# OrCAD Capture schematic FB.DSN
size C
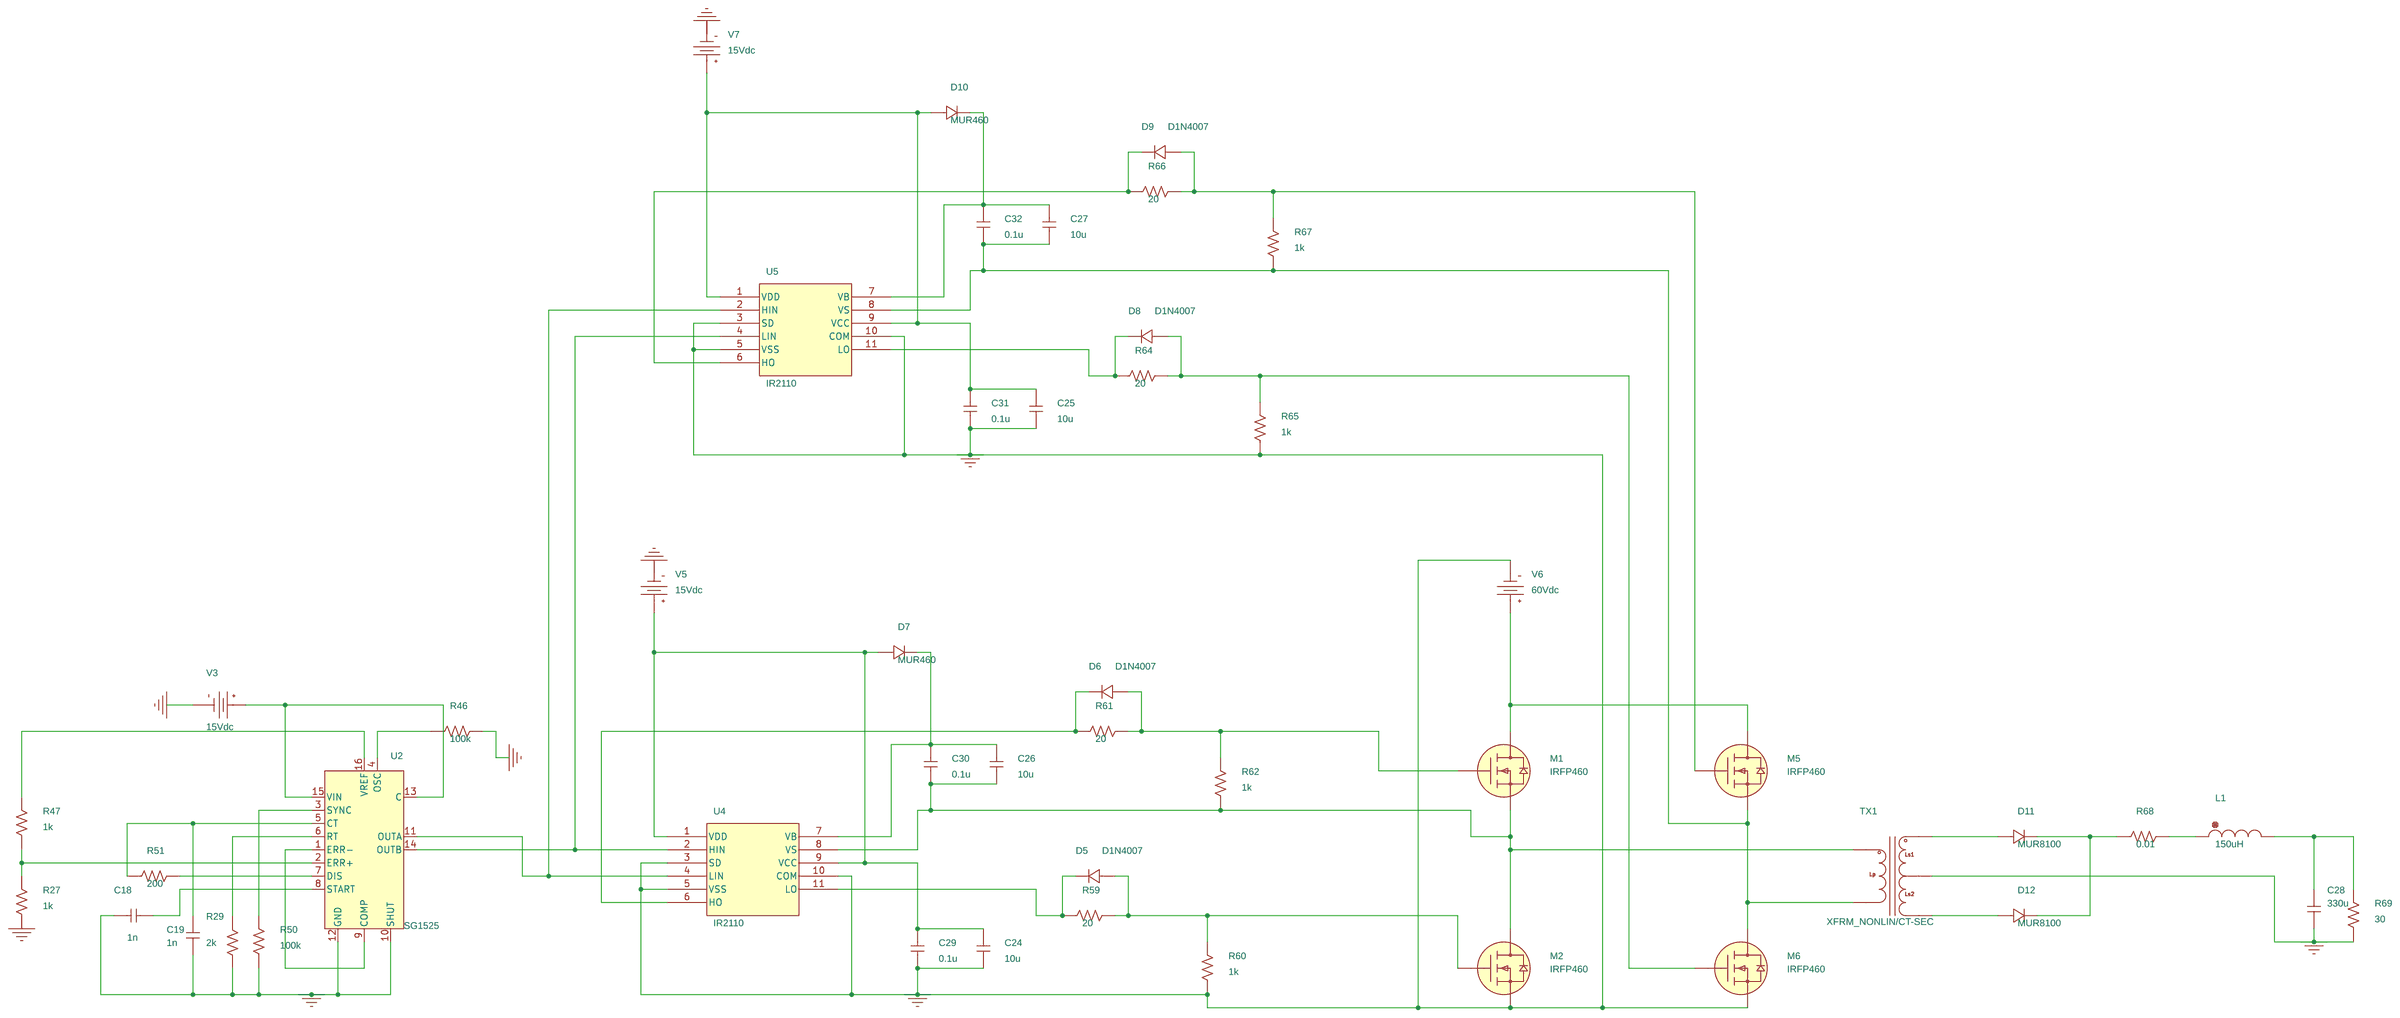
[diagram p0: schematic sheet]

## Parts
C18  1n  [RAD/CK05]
C19  1n  [RAD/CK05]
C24  10u  [RAD/CK05]
C25  10u  [RAD/CK05]
C26  10u  [RAD/CK05]
C27  10u  [RAD/CK05]
C28  330u  [RAD/CK05]
C29  0.1u  [RAD/CK05]
C30  0.1u  [RAD/CK05]
C31  0.1u  [RAD/CK05]
C32  0.1u  [RAD/CK05]
D5  D1N4007  [DO-41]
D6  D1N4007  [DO-41]
D7  MUR460  [DO-27]
D8  D1N4007  [DO-41]
D9  D1N4007  [DO-41]
D10  MUR460  [DO-27]
D11  MUR8100  [TO220AC]
D12  MUR8100  [TO220AC]
L1  150uH  [DISC/.350x.175/LS.200x.100/.034]
M1  IRFP460  [TO247AC]
M2  IRFP460  [TO247AC]
M5  IRFP460  [TO247AC]
M6  IRFP460  [TO247AC]
R27  1k  [AX/RC05]
R29  2k  [AX/RC05]
R46  100k  [AX/RC05]
R47  1k  [AX/RC05]
R50  100k  [AX/RC05]
R51  200  [AX/RC05]
R59  20  [AX/RC05]
R60  1k  [AX/RC05]
R61  20  [AX/RC05]
R62  1k  [AX/RC05]
R64  20  [AX/RC05]
R65  1k  [AX/RC05]
R66  20  [AX/RC05]
R67  1k  [AX/RC05]
R68  0.01  [AX/RC05]
R69  30  [AX/RC05]
TX1  XFRM_NONLIN/CT-SEC
U2  SG1525  [DIP.100/16/W.300/L.900]
U4  IR2110
U5  IR2110
V3  VDC
V5  VDC
V6  VDC
V7  VDC

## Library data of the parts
C18 C19 C26-C28 = C
C24 C25 C29-C32 = C: IC: 15V
D5 D6 D8 D9 = D1N4007
D7 D10 = MUR460
D11 D12 = MUR8100
L1 = L
M1 M2 M5 M6 = IRFP460
R27 R29 R46 R47 R50 R51 R59-R62 R64-R69 = R
TX1 = XFRM_NONLIN_CT-SEC: LP_TURNS: 100
U2 = SG1525: DEADTIME: 1us; PERIOD: 20us
U4 U5 = IR2110
V3 V5 V7 = VDC: DC: 15Vdc
V6 = VDC: DC: 60Vdc

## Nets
0: C18.2 C19.2 C24.1 C25.1 C28.1 C29.1 C31.1 M2.3(S) M6.3(S) R27.1 R29.2 R46.2 R50.1 R60.1 R65.1 R69.1 TX1.3(5) U2.10(SHUT) U2.12(GND) U4.3(SD) U4.5(VSS) U4.10(COM) U5.3(SD) U5.5(VSS) U5.10(COM) V3.1(-) V5.1(-) V6.1(-) V7.1(-)
N25945: U2.1(ERR-) U2.9(COMP)
N25953: R47.2 U2.16(VREF)
N25993: R46.1 U2.4(OSC)
N26001: U2.13(C) U2.15(VIN) V3.0(+)
N26089: R27.2 R47.1 U2.2(ERR+)
N26117: R29.1 U2.6(RT)
N26177: C19.1 R51.1 U2.5(CT)
N26241: C18.1 U2.8(START)
N26301: R50.2 U2.3(SYNC)
N26349: R51.2 U2.7(DIS)
N27056: U2.11(OUTA) U4.4(LIN) U5.2(HIN)
N30740: C24.2 C29.2 D7.2 U4.1(VDD) U4.9(VCC) V5.0(+)
N30764: D5.2 R59.1 U4.11(LO)
N30772: D5.1 M2.2(G) R59.2 R60.2
N30852: C26.2 C30.2 D7.1 U4.7(VB)
N30872: C26.1 C30.1 M1.3(S) M2.1(D) R62.1 TX1.0(1) U4.8(VS)
N30892: D6.2 R61.1 U4.6(HO)
N30900: D6.1 M1.2(G) R61.2 R62.2
N32139: U2.14(OUTB) U4.2(HIN) U5.4(LIN)
N32632: M1.1(D) M5.1(D) V6.0(+)
N38039: C25.2 C31.2 D10.2 U5.1(VDD) U5.9(VCC) V7.0(+)
N38059: D8.2 R64.1 U5.11(LO)
N38063: D8.1 M6.2(G) R64.2 R65.2
N38127: C27.2 C32.2 D10.1 U5.7(VB)
N38147: C27.1 C32.1 M5.3(S) M6.1(D) R67.1 TX1.1(3) U5.8(VS)
N38167: D9.2 R66.1 U5.6(HO)
N38171: D9.1 M5.2(G) R66.2 R67.2
N42252: D11.3(1) TX1.2(4)
N42313: D11.1(2) D12.1(2) R68.1
N42317: L1.1 R68.2
N42321: C28.2 L1.2 R69.2
N42360: D12.3(1) TX1.4(6)
